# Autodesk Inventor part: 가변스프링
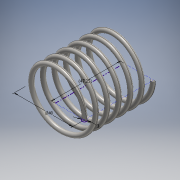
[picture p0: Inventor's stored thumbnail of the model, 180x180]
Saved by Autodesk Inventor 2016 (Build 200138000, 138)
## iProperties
Created: 2018-02
Part Number: 가변스프링
Material: 스테인레스 스틸
Document SubType Name: Modeling
Designer: 605-04
Density: 8 g/cm^3
Appearance: 반연마
Mass: 42.0438 g
Surface Area: 70.8946 cm^2
Volume: 5.25548 cm^3
Author: 605-04
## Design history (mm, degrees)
sketch "스케치1"
  geometry: L1 (0, 0)-(0, 47.25); L2 (0, 47.25)-(20, 47.25); L3 (20, 47.25)-(20, 0); L4 (20, 0)-(0, 0); C1 r 1.5 at (20, 0)
  constraints: 8 end point, 3 perpendicular, 1 centre point, 1 coincident, 1 vertical
  dimensions: "d0" = 47.25 distance of L1.start L1.end (derived); "d1" = 40 diameter of L3 L1; "d2" = 3 diameter of C1
feature "코일1" sketch "스케치1" pitch "d3" = 10; turns "d5" = 6; dims "d4" = 47.25 (= d0), "d6" = 0, angle "d7" = 90 deg, angle "d8" = 90 deg, "d9" = 0, "d10" = 0
sketch "스케치2"
  geometry: L1 (-18.5, 0)-(-21.5, 0) reference; L2 (-18.5, 0)-(-21.5, 0) reference; 1 further point
  constraints: 2 horizontal alignment
extrude "돌출1" cut sketch "스케치2" distance "d11" = 10; taper "d12" = 0 deg
node "작업 평면1"
sketch "스케치3"
  geometry: L1 (18.5, 0)-(21.5, 0) reference; 1 further point
  constraints: 1 horizontal alignment
extrude "돌출2" cut sketch "스케치3" distance "d14" = 10; taper "d15" = 0 deg
node "솔리드1"
node "절단 모서리 투영1"
node "절단 모서리 투영2"
node "절단 모서리 투영3"
other parameters: "d13" = 90 deg
